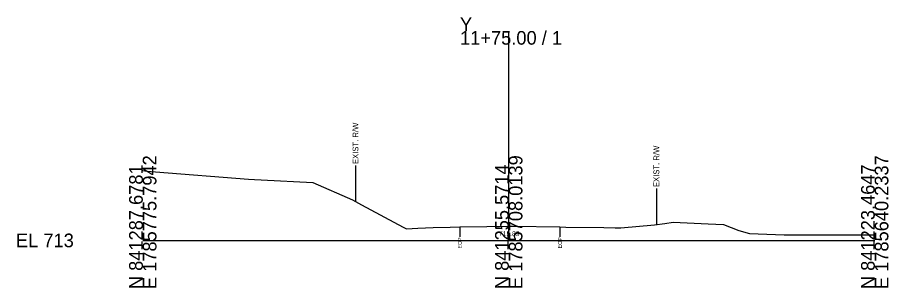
# Model space of a CAD drawing. Extents: x -26 to 153, y 990 to 3546.
# Drawn here: x -25.7 to 152.8, y 3490.3 to 3545.8 of the extents above; entities that cross this region are included whole.
import ezdxf

# ---------------------------------------------------------------- set-up
doc = ezdxf.new("R2010")
doc.units = 0
for name, color, linetype in [('Exist Cross Section Cell', 7, 'Continuous'), ('Exist XS Center Line Elevation Label', 7, 'Continuous'), ('Exist XS Ground Line', 7, 'Continuous'), ('Old_Level_10', 7, 'Continuous')]:
    doc.layers.add(name, color=color, linetype=linetype)

msp = doc.modelspace()

# ---------------------------------------------------------------- linework, layer by layer
at = {"layer": 'Exist Cross Section Cell'}
for p, q in [((75, 3500), (75, 3542.99)), ((0, 3500), (75, 3500)), ((75, 3500), (150, 3500))]:
    msp.add_line(p, q, dxfattribs=at)
at = {"layer": 'Exist XS Ground Line'}
msp.add_lwpolyline([(0, 3514.33), (0.85, 3514.25), (2.6, 3514.09), (21.64, 3512.58), (22.9, 3512.52), (24.28, 3512.42), (34.87, 3511.9), (42.95, 3508.31), (44.85, 3507.3), (53.37, 3502.73), (54.04, 3502.38), (56.4, 3502.5), (59.52, 3502.67), (62.97, 3502.72), (64.99, 3502.77), (70.48, 3502.84), (75, 3502.89), (75.47, 3502.9), (75.84, 3502.9), (85.5, 3502.81), (86.72, 3502.75), (94.47, 3502.63), (96.78, 3502.58), (97.95, 3502.59), (104.84, 3503.17), (107, 3503.5), (108.71, 3503.76), (115.84, 3503.39), (119.03, 3503.27), (122.15, 3502.02), (124.32, 3501.4), (131.41, 3501.16), (132.41, 3501.13), (134.44, 3501.13), (134.93, 3501.13), (137.85, 3501.13), (138.46, 3501.13), (139.04, 3501.13), (150, 3501.13)], dxfattribs=at)
at = {"layer": 'Old_Level_10'}
for p, q in [((43.59, 3515.37), (43.59, 3507.97)), ((105.25, 3510.64), (105.25, 3503.23)), ((64.99, 3502.77), (64.99, 3500.71)), ((85.5, 3502.81), (85.5, 3500.76))]:
    msp.add_line(p, q, dxfattribs=at)

# ---------------------------------------------------------------- texts
at = {"layer": 'Exist Cross Section Cell'}
for s, p in [('Y', (65, 3542.99)), ('11+75.00 / 1', (65, 3540.19)), ('EL 713', (-26, 3498.6))]:
    msp.add_text(s, height=2.8, dxfattribs=at).set_placement(p)
for s, p in [('E 1785775.7942', (2.8, 3490)), ('E 1785708.0139', (77.8, 3490)), ('E 1785640.2337', (152.8, 3490)), ('N 841287.6781', (0, 3490)), ('N 841255.5714', (75, 3490)), ('N 841223.4647', (150, 3490))]:
    msp.add_text(s, height=2.8, rotation=90, dxfattribs=at).set_placement(p)
at = {"layer": 'Exist XS Center Line Elevation Label'}
msp.add_text('715.89', height=1, dxfattribs=at).set_placement((72.99, 3500.89))
at = {"layer": 'Old_Level_10'}
for s, height, p in [('EXIST. R/W', 1.181, (44.18, 3515.67)), ('EXIST. R/W', 1.181, (105.84, 3510.94)), ('EOP', 0.787, (65.38, 3498.32)), ('EOP', 0.787, (85.89, 3498.36))]:
    msp.add_text(s, height=height, rotation=90, dxfattribs=at).set_placement(p)

doc.saveas('drawing.dxf')
